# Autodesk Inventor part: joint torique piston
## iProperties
Created: 2002-03
Part Number: joint torique piston
Material: Par défaut
Document SubType Name: Modélisation
Designer: User
Control State: 0
Master: False
Checked Out: False
Shininess: 20.0
Length Units: 11269
Angle Units: 11279
Time Units: 11290
Mass Units: 11283
Length Display Precision: 3
Angle Display Precision: 2
Density: 0.0
Volumn: 0.0
Area: 0.0
PropertySet Name: Model Information
Author: User
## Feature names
1. Révolution1 [Revolution]
